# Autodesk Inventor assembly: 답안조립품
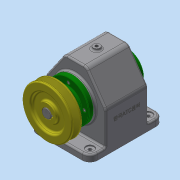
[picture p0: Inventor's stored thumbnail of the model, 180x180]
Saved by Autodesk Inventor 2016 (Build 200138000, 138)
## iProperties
Created: 2022-12
Part Number: 답안조립품
Material: 일반
Document SubType Name: Assembly
Designer: PC-1-2
Author: PC-1-2
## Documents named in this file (15)
- C:\Users\PC-1-2\Desktop\721206V1004\답안조립품.iam
- C:\Users\PC-1-2\Desktop\721206V1004\본체.ipt
- C:\Users\PC-1-2\Desktop\721206V1004\뒤커버.ipt
- C:\Users\PC-1-2\Desktop\721206V1004\앞커버.ipt
- C:\Users\PC-1-2\Desktop\721206V1004\오일 실 17 x 32 x 8.ipt
- C:\Users\PC-1-2\Desktop\721206V1004\베어링 6203.ipt
- C:\Users\PC-1-2\Desktop\721206V1004\축.ipt
- C:\Users\PC-1-2\Desktop\721206V1004\키 - 6 x 6 x 22.ipt
- C:\Users\PC-1-2\Desktop\721206V1004\스퍼기어.ipt
- C:\Users\PC-1-2\Desktop\721206V1004\칼라.ipt
- C:\Users\PC-1-2\Desktop\721206V1004\키 - 5 x 5 x 18.ipt
- C:\Users\PC-1-2\Desktop\721206V1004\V-벨트풀리.ipt
- C:\Users\PC-1-2\Desktop\721206V1004\멈춤나사 - M4x10.ipt
- C:\Users\PC-1-2\Desktop\721206V1004\볼트 M3 x 10.ipt
- C:\Users\PC-1-2\Desktop\721206V1004\볼트 M3 x 8.ipt
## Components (9 placed, 3 different names)
1. V-벨트풀리:1
2. ISO 4762 M3 x 10:1
3. ISO 4762 M3 x 10:2
4. ISO 4762 M3 x 10:3
5. ISO 4762 M3 x 10:4
6. ISO 4762 M3 x 8:1
7. ISO 4762 M3 x 8:2
8. ISO 4762 M3 x 8:3
9. ISO 4762 M3 x 8:4
